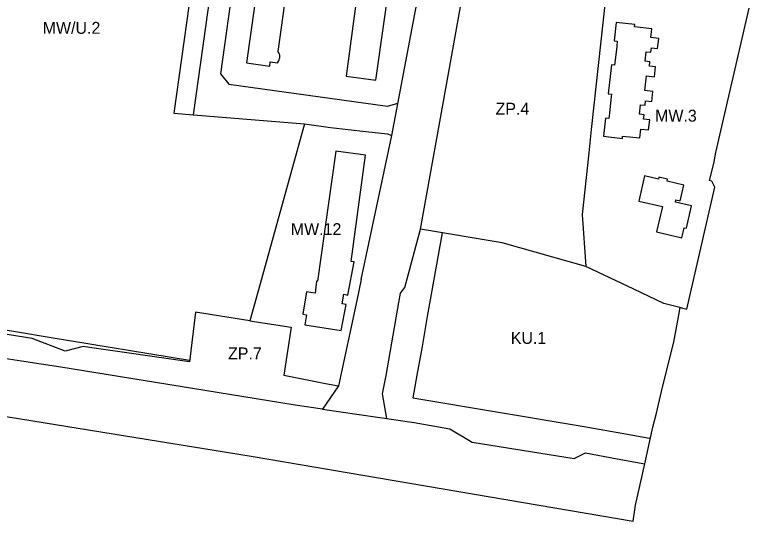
# Model space of a CAD drawing. Extents: x 7427060 to 7429122, y 5545301 to 5546237.
# Drawn here: x 7428222.9 to 7428530.8, y 5545301.4 to 5545513.7 of the extents above; entities that cross this region are included whole.
import ezdxf

# ---------------------------------------------------------------- set-up
doc = ezdxf.new("R2010")
doc.units = 0
for name, color, linetype in [('LIN_Linia Zabudowy Nieprzekraczalna', 7, 'Continuous'), ('LIN_Linia Zabudowy Obowiązujaca', 7, 'Continuous'), ('LIN_Linie Rozgraniczajace', 7, 'Continuous'), ('TXT_Oznaczenia Przeznaczenia', 7, 'Continuous')]:
    doc.layers.add(name, color=color, linetype=linetype)

msp = doc.modelspace()

# ---------------------------------------------------------------- linework, layer by layer
at = {"layer": 'LIN_Linia Zabudowy Nieprzekraczalna'}
for points in [[(7428402.08, 5545422.26), (7428395.77, 5545387.18), (7428393.62, 5545374.66), (7428391.48, 5545362.62), (7428389.83, 5545353.12)], [(7428389.83, 5545353.12), (7428460.73, 5545341.32), (7428477.31, 5545338.31), (7428488.88, 5545336.21)]]:
    msp.add_lwpolyline(points, dxfattribs=at)
at = {"layer": 'LIN_Linia Zabudowy Obowiązujaca'}
for points in [[(7428368.68, 5545539.25), (7428361.9, 5545487.97), (7428374.32, 5545486.19), (7428381.54, 5545537.45)], [(7428325.05, 5545529.27), (7428320.05, 5545493.53), (7428329.82, 5545492.11), (7428330.06, 5545493.86), (7428333.05, 5545493.44), (7428333.36, 5545493.91), (7428333.63, 5545494.33), (7428333.83, 5545494.79), (7428333.97, 5545495.27), (7428334.05, 5545495.76), (7428334.05, 5545496.26), (7428333.99, 5545496.76), (7428333.85, 5545497.24), (7428333.66, 5545497.7), (7428333.4, 5545498.13), (7428333.28, 5545498.28), (7428337.46, 5545527.61)], [(7428183.42, 5545387.33), (7428193.92, 5545385.7), (7428223.31, 5545380.89), (7428238.16, 5545378.37), (7428296.24, 5545368.97)]]:
    msp.add_lwpolyline(points, dxfattribs=at)
for points in [[(7428482.72, 5545508.59), (7428482.81, 5545509.58), (7428474.98, 5545510.45), (7428474.11, 5545502.73), (7428475.43, 5545502.58), (7428475.19, 5545500.36), (7428474.56, 5545494.67), (7428474.31, 5545492.47), (7428472.99, 5545492.61), (7428471.68, 5545480.52), (7428473, 5545480.37), (7428472.75, 5545478.12), (7428472.12, 5545472.47), (7428471.87, 5545470.22), (7428470.55, 5545470.37), (7428469.7, 5545462.71), (7428477.57, 5545461.82), (7428477.66, 5545462.81), (7428484.93, 5545462.02), (7428485.33, 5545465.74), (7428488.57, 5545465.38), (7428489.04, 5545469.6), (7428486.46, 5545469.9), (7428486.66, 5545471.74), (7428484.69, 5545471.95), (7428485.13, 5545475.94), (7428487.11, 5545475.71), (7428487.32, 5545477.53), (7428489.89, 5545477.27), (7428490.35, 5545481.5), (7428486.97, 5545481.87), (7428487.65, 5545487.98), (7428491.02, 5545487.61), (7428491.48, 5545491.85), (7428488.94, 5545492.11), (7428489.12, 5545493.92), (7428487.13, 5545494.16), (7428487.57, 5545498.15), (7428489.56, 5545497.93), (7428489.78, 5545499.76), (7428492.33, 5545499.47), (7428492.8, 5545503.71), (7428489.56, 5545504.06), (7428489.98, 5545507.78)], [(7428357.46, 5545456.47), (7428349.89, 5545401.98), (7428349.47, 5545402.05), (7428348.81, 5545397.06), (7428345.25, 5545397.63), (7428343.73, 5545388.15), (7428345.21, 5545387.92), (7428344.54, 5545383.77), (7428359.7, 5545381.33), (7428361.79, 5545392.2), (7428360.12, 5545392.51), (7428360.91, 5545396.57), (7428362.57, 5545396.19), (7428365.25, 5545410.07), (7428363.97, 5545410.24), (7428369.99, 5545454.78)], [(7428491.91, 5545422.66), (7428502.55, 5545420.2), (7428503.52, 5545424.4), (7428504.43, 5545424.19), (7428506.55, 5545433.52), (7428499.79, 5545435.07), (7428500.03, 5545436.15), (7428501.81, 5545435.74), (7428503.31, 5545442.27), (7428496.3, 5545443.91), (7428496.5, 5545444.78), (7428492.9, 5545445.62), (7428492.7, 5545444.75), (7428486.85, 5545446.11), (7428484.41, 5545435.5), (7428494.4, 5545433.24)]]:
    msp.add_lwpolyline(points, close=True, dxfattribs=at)
at = {"layer": 'LIN_Linie Rozgraniczajace'}
for p, q in [((7428312.62, 5545484.56), (7428379.21, 5545475.28)), ((7428379.21, 5545475.28), (7428383.56, 5545476.63))]:
    msp.add_line(p, q, dxfattribs=at)
for points in [[(7428344.43, 5545708.9), (7428342.35, 5545708.87), (7428341.16, 5545708.35), (7428339.54, 5545706.88), (7428337.52, 5545691.03), (7428333.26, 5545660.2), (7428327.86, 5545621.48), (7428319.08, 5545559.65), (7428314.95, 5545530.02), (7428309.18, 5545488.82), (7428312.62, 5545484.56)], [(7428392.97, 5545423.8), (7428404.8, 5545489.73), (7428417.42, 5545559.93), (7428425.55, 5545604.05), (7428431.66, 5545635.8), (7428435.42, 5545655.33), (7428438.5, 5545674.95)], [(7428311.75, 5545630.49), (7428303.59, 5545572.14), (7428301.03, 5545553.81), (7428299.2, 5545541.28), (7428289.56, 5545472.35), (7428297.89, 5545471.68)], [(7428475.27, 5545561.56), (7428472.98, 5545542.22), (7428471.55, 5545529.52), (7428464.57, 5545465.61), (7428463.5, 5545455.77), (7428460.68, 5545429.92), (7428462.27, 5545408.23)], [(7428368.18, 5545402.78), (7428380.98, 5545463), (7428398.84, 5545557.64)], [(7428297.89, 5545471.68), (7428309.1, 5545551.64)], [(7428070.75, 5545369.4), (7428321.97, 5545328.77), (7428482.16, 5545301.44), (7428483.07, 5545308.25), (7428486.95, 5545325.58), (7428489.1, 5545335.15), (7428490.38, 5545340.86), (7428491.82, 5545346.8), (7428493.55, 5545353.99), (7428494.6, 5545358.2), (7428499.16, 5545376.51), (7428501.42, 5545388.66), (7428501.85, 5545390.98), (7428504.61, 5545390.31), (7428516.31, 5545441.43), (7428515.01, 5545443.99), (7428514.03, 5545444.21), (7428515.86, 5545451.32), (7428516.73, 5545455.86), (7428530.77, 5545516.4)], [(7428297.89, 5545471.68), (7428344.44, 5545467.96), (7428355.33, 5545466.36), (7428370.06, 5545464.78), (7428379.14, 5545463.81), (7428380.98, 5545463)], [(7428344.44, 5545467.96), (7428326.47, 5545403.44), (7428321.46, 5545385.45)], [(7428378.83, 5545344.53), (7428377.1, 5545354.86), (7428378.55, 5545362.54), (7428383.89, 5545393.03), (7428384.54, 5545396.97), (7428386.36, 5545399.37), (7428392.97, 5545423.8)], [(7428502.78, 5545390.75), (7428494.94, 5545392.69), (7428482.42, 5545398.64), (7428462.27, 5545408.23), (7428427.27, 5545418.02), (7428392.97, 5545423.8)], [(7428368.18, 5545402.78), (7428366.29, 5545393.93), (7428358.61, 5545358.13), (7428351.95, 5545348.48)], [(7428321.46, 5545385.45), (7428298.76, 5545389.03), (7428296.16, 5545368.3), (7428254.28, 5545374.29), (7428251.6, 5545374.71), (7428244.03, 5545372.76), (7428230.31, 5545378.06), (7428204.73, 5545382.1), (7428198.2, 5545383.06), (7428178.97, 5545386.33), (7428176.92, 5545386.67)], [(7428321.46, 5545385.45), (7428338.75, 5545382.73), (7428335.75, 5545362.64), (7428353.14, 5545359.1), (7428358.61, 5545358.13)], [(7428351.95, 5545348.48), (7428340.49, 5545350.16), (7428291.51, 5545358.04), (7428242.24, 5545366.03), (7428225.77, 5545368.53), (7428196.66, 5545372.94)], [(7428351.95, 5545348.48), (7428390.28, 5545342.85), (7428405.27, 5545340.22), (7428414.62, 5545334.65), (7428457.43, 5545327.71), (7428462.19, 5545330.08), (7428475.38, 5545327.68), (7428486.95, 5545325.58)]]:
    msp.add_lwpolyline(points, dxfattribs=at)

# ---------------------------------------------------------------- texts
at = {"layer": 'TXT_Oznaczenia Przeznaczenia'}
for s, p in [('MW/U.2', (7428234.69, 5545505.64)), ('MW.3', (7428491.29, 5545468.84)), ('KU.1', (7428430.83, 5545375.77)), ('ZP.7', (7428312.34, 5545369.25))]:
    msp.add_text(s, height=5, rotation=360, dxfattribs=at).set_placement(p)
for s, p in [('ZP.4', (7428424.45, 5545471.75)), ('MW.12', (7428338.65, 5545421.32))]:
    msp.add_text(s, height=5, dxfattribs=at).set_placement(p)

doc.saveas('drawing.dxf')
